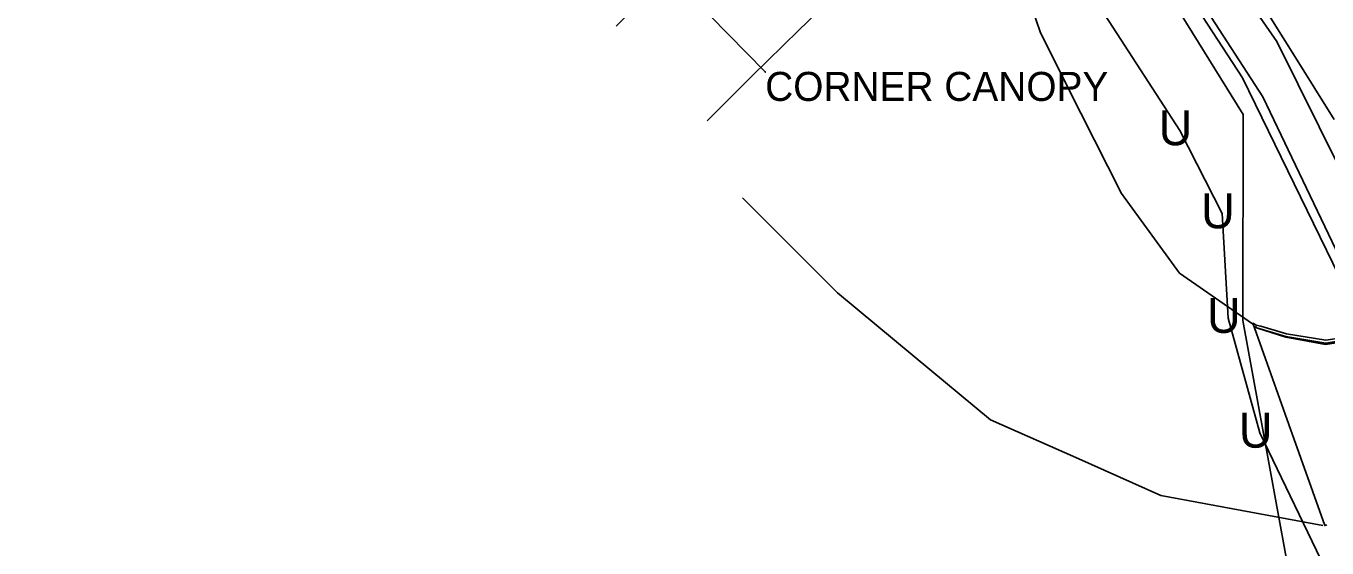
# Model space of a CAD drawing. Extents: x 1050807 to 1053552, y 395828 to 398415.
# Drawn here: x 1051813.5 to 1052037.5, y 397799.4 to 397889.3 of the extents above; entities that cross this region are included whole.
import ezdxf

# ---------------------------------------------------------------- set-up
doc = ezdxf.new("R2010")
doc.units = 0
for name, color, linetype in [('Default', 7, 'Continuous'), ('S_CURB', 7, 'Continuous'), ('S_DITCHLINE', 7, 'Continuous'), ('S_EDGE_CONCRETE', 7, 'Continuous'), ('S_EDGE_PAVEMENT', 7, 'Continuous'), ('S_GRAVEL_ROAD', 7, 'Continuous'), ('S_MISC_STRUCTURES', 7, 'Continuous'), ('S_MISC_STRUCTURES_ANNOT', 7, 'Continuous'), ('S_MSC_PT_SYM', 7, 'Continuous'), ('S_SHOULDER', 7, 'Continuous'), ('S_UNDERGROUND_CABLE', 7, 'Continuous'), ('S_UTL_PT_SYM', 7, 'Continuous'), ('S_WATER_UTILITIES', 7, 'Continuous')]:
    doc.layers.add(name, color=color, linetype=linetype)

msp = doc.modelspace()

# ---------------------------------------------------------------- linework, layer by layer
at = {"layer": 'S_CURB'}
for points in [[(1052050.31, 397840.95), (1052049.6, 397840.16), (1052046.66, 397837.56), (1052043.32, 397836.12), (1052037.27, 397835.2), (1052030.49, 397836.28), (1052026.08, 397837.6), (1052025.26, 397837.75), (1052025.2, 397837.4), (1052025.95, 397837.16), (1052030.36, 397835.85), (1052037.25, 397834.67), (1052043.52, 397835.7), (1052046.94, 397837.22), (1052049.93, 397839.91), (1052050.76, 397840.38), (1052050.38, 397840.93)], [(1052050.19, 397839.99), (1052047.1, 397836.98), (1052043.53, 397835.43), (1052037.22, 397834.47), (1052030.38, 397835.68), (1052025.31, 397837.34)]]:
    msp.add_lwpolyline(points, dxfattribs=at)
at = {"layer": 'S_DITCHLINE'}
msp.add_lwpolyline([(1052044.57, 397837.02), (1052042.71, 397843.02), (1052034.56, 397860.05), (1052026.4, 397877.08), (1052014.15, 397896.07), (1052001.9, 397915.06), (1051993.3, 397924.87), (1051984.69, 397934.68), (1051976.08, 397944.49), (1051967.48, 397954.3), (1051953.82, 397966.69), (1051940.17, 397979.07), (1051928.17, 397988.62), (1051927.23, 397987.62), (1051944.65, 397973.64), (1051959.58, 397959.55), (1051974.51, 397945.46), (1051988.4, 397928.84), (1052002.28, 397912.21), (1052012.59, 397896.28), (1052022.89, 397880.34), (1052031.8, 397862.09), (1052040.71, 397843.83), (1052043.64, 397836.55)], dxfattribs=at)
at = {"layer": 'S_EDGE_CONCRETE'}
for points in [[(1051930.77, 397872.97), (1051938.43, 397880.67), (1051946.56, 397888.54), (1051954.11, 397895.93), (1051958.55, 397891.51), (1051970.79, 397903.35), (1051958.14, 397916.38), (1051946.42, 397928.32), (1051934.2, 397916.52), (1051938.25, 397912.4), (1051931.21, 397905.3), (1051922.4, 397896.53), (1051915.1, 397889.23)], [(1052025.23, 397837.85), (1052024.68, 397838.09), (1052030.88, 397820.69), (1052037.07, 397803.28), (1052037.42, 397803.39)]]:
    msp.add_lwpolyline(points, dxfattribs=at)
at = {"layer": 'S_EDGE_PAVEMENT'}
msp.add_lwpolyline([(1052038.69, 397873.19), (1052032.04, 397883.85), (1052025.39, 397894.51), (1052018.74, 397905.17), (1052012.09, 397915.83), (1052004.02, 397925.46), (1051995.95, 397935.08), (1051987.88, 397944.7), (1051979.81, 397954.32), (1051970.07, 397963.03), (1051960.33, 397971.74), (1051950.59, 397980.46), (1051940.85, 397989.17), (1051920.67, 398003.53), (1051900.02, 398015.7), (1051879.38, 398027.86), (1051867.4, 398032.67), (1051855.43, 398037.49), (1051843.45, 398042.3), (1051831.48, 398047.11), (1051807.63, 398052.86)], dxfattribs=at)
at = {"layer": 'S_GRAVEL_ROAD'}
for points in [[(1051907.2, 398003.55), (1051915.88, 398002.91), (1051917.6, 397989.1), (1051925.25, 397976.64), (1051940.24, 397961.7), (1051955.22, 397946.76), (1051966.38, 397933.09), (1051977.54, 397919.42), (1051982.83, 397903.76), (1051988.12, 397888.11), (1051995.11, 397874.29), (1052002.09, 397860.47), (1052012.08, 397846.73), (1052024.66, 397838)], [(1052036.72, 397803.29), (1052022.79, 397805.87), (1052008.86, 397808.45), (1051994.21, 397814.96), (1051979.56, 397821.47), (1051966.38, 397832.39), (1051953.2, 397843.32), (1051936.87, 397859.67)]]:
    msp.add_lwpolyline(points, dxfattribs=at)
at = {"layer": 'S_MISC_STRUCTURES'}
msp.add_line((1051940.75, 397881.38), (1051923.66, 397898.86), dxfattribs=at)
at = {"layer": 'S_MSC_PT_SYM'}
msp.add_lwpolyline([(1051940.75, 397881.38), (1051940.75, 397881.43), (1051940.75, 397881.38), (1051940.7, 397881.38), (1051940.75, 397881.38), (1051940.75, 397881.33), (1051940.75, 397881.38), (1051940.8, 397881.38)], dxfattribs=at)
at = {"layer": 'S_SHOULDER'}
msp.add_lwpolyline([(1052050.55, 397842.58), (1052039.7, 397864.61), (1052028.85, 397886.64), (1052021.35, 397897.42), (1052013.86, 397908.2), (1052006.37, 397918.98), (1051998.87, 397929.76), (1051981.88, 397947.71), (1051964.88, 397965.66), (1051950.67, 397977.79), (1051936.46, 397989.93), (1051922.29, 398000.29)], dxfattribs=at)
at = {"layer": 'S_UNDERGROUND_CABLE'}
for p, q in [((1052012.11, 397871.29), (1051984.34, 397914.25)), ((1052019.42, 397857), (1052012.11, 397871.29)), ((1052020.43, 397838.99), (1052019.42, 397857)), ((1052025.92, 397819.22), (1052020.43, 397838.99)), ((1052039.29, 397791.49), (1052025.92, 397819.22))]:
    msp.add_line(p, q, dxfattribs=at)
at = {"layer": 'S_UTL_PT_SYM'}
for points in [[(1052023.03, 397874.07), (1052023.03, 397874.12), (1052023.03, 397874.07), (1052022.98, 397874.07), (1052023.03, 397874.07), (1052023.03, 397874.02), (1052023.03, 397874.07), (1052023.08, 397874.07)], [(1052022.97, 397838.59), (1052022.97, 397838.64), (1052022.97, 397838.59), (1052022.92, 397838.59), (1052022.97, 397838.59), (1052022.97, 397838.54), (1052022.97, 397838.59), (1052023.02, 397838.59)]]:
    msp.add_lwpolyline(points, dxfattribs=at)
at = {"layer": 'S_WATER_UTILITIES'}
for p, q in [((1052023.03, 397874.07), (1051999.41, 397912.24)), ((1052022.97, 397838.59), (1052023.03, 397874.07)), ((1052032.43, 397786.88), (1052022.97, 397838.59))]:
    msp.add_line(p, q, dxfattribs=at)

# ---------------------------------------------------------------- texts
at = {"layer": 'Default'}
for p in [(1052008.48, 397868.75), (1052015.79, 397854.45), (1052016.8, 397836.44), (1052022.29, 397816.68)]:
    msp.add_text('U', height=6, dxfattribs=at).set_placement(p)
at = {"layer": 'S_MISC_STRUCTURES_ANNOT'}
msp.add_text('CORNER CANOPY', height=5, dxfattribs=at).set_placement((1051940.75, 397876.38))

doc.saveas('drawing.dxf')
